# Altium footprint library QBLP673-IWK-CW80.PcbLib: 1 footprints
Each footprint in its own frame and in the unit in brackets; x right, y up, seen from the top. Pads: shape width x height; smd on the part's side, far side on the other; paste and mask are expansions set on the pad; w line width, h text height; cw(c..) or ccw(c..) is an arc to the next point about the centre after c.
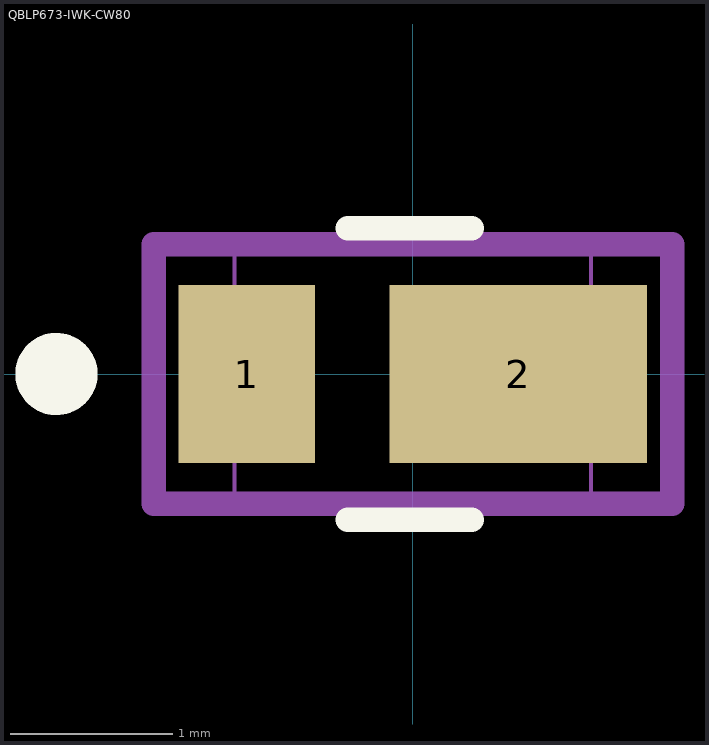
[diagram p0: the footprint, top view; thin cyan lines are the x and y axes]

## QBLP673-IWK-CW80 [mm]
pads (2):
  rect 0.84x1.1 smd paste+0 mask+0: 1(-1.025,0)
  rect 1.59x1.1 smd paste+0 mask+0: 2(0.65,0)
Top Overlay:
  circle w0.254: c-2.2,0 r0.127
  lines w0.152: -0.4,-0.9 0.362,-0.9 ; -0.4,0.9 0.362,0.9
Mechanical 5:
  lines w0.15: -1.6,-0.8 1.6,-0.8 1.6,0.8 -1.6,0.8 -1.6,-0.8
Mechanical 13:
  lines w0.025: -1.1,-0.8 1.1,-0.8 1.1,0.8 -1.1,0.8 -1.1,-0.8
Mechanical 15:
  lines w0.15: -1.6,-0.8 -1.6,0.8 1.6,0.8 1.6,-0.8 -1.6,-0.8
3D body "QBLP673.step": height 0.55, standoff 0, extent -1.088,-0.8 1.112,0.8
